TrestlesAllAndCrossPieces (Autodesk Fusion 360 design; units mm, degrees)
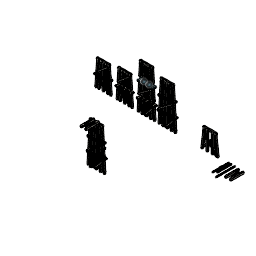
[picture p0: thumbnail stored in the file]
parameter "d35" = 40
parameter "d36" = 14
parameter "d37" = 14
sketch "Sketch1" plane through (0, 0, 0) normal (0, 0, 1) x axis (1, 0, 0)
  line L1 (1, 0) -> (0, 0)
  line L2 (1, 2) -> (1, 0)
  line L3 (0, 2) -> (1, 2)
  line L4 (0, 0) -> (0, 2)
  point P1 (0, 0)
  point P2 (0, 0)
  point P3 (1, 0)
  point P5 (0, 2)
  horizontal L1
  vertical L2
  horizontal L3
  vertical L4
  coincident P1 P2
  dimension "d1" distance P2 P3 = 1
  dimension "d2" distance P2 P5 = 2
sketch "Sketch2" plane through (0, 0, 0) normal (0, 0, 1) x axis (1, 0, 0)
  line L1 (-6.5, 0) -> (-5, 0)
  line L2 (-6.5, 2) -> (-6.5, 0)
  line L3 (-5, 2) -> (-6.5, 2)
  line L4 (-5, 0) -> (-5, 2)
  line L5 (-11.5, 0) -> (-10, 0)
  line L6 (-11.5, 2) -> (-11.5, 0)
  line L7 (-10, 2) -> (-11.5, 2)
  line L8 (-10, 0) -> (-10, 2)
  point P2 (-5, 0)
  point P3 (-6.5, 0)
  point P5 (-5, 2)
  point P6 (-10, 0)
  point P7 (-11.5, 0)
  point P9 (-10, 2)
  horizontal L1
  vertical L2
  horizontal L3
  vertical L4
  horizontal L5
  vertical L6
  horizontal L7
  vertical L8
  dimension "d5" distance P2 P3 = 1.5
  dimension "d6" distance P2 P5 = 2
  dimension "d7" distance P6 P7 = 1.5
  dimension "d8" distance P6 P9 = 2
extrude "Extrude2" new body sketch "Sketch2" profile of L1 L2 L3 L4 along normal blind 31 bodies "CrossPieceHorz31mm"
extrude "Extrude3" new body sketch "Sketch2" profile of L5 L6 L7 L8 along normal blind 36 bodies "CrossPieceDiagonal"
work_plane "WorkPlane1"
sketch "Sketch3" plane through (0, 2, 0) normal (0, 1, 0) x axis (-1, 0, 0)
  line L1 (11.5, 0) -> (10, 0)
  line L2 (11.5, 36) -> (11.5, 0)
  line L3 (10, 36) -> (11.5, 36)
  line L4 (10, 0) -> (10, 36)
  line L5 (10.75, 18) -> (10, 18)
  line L6 (10.75, 19.5) -> (10.75, 18)
  line L7 (10, 19.5) -> (10.75, 19.5)
  line L8 (10, 18) -> (10, 19.5)
  line L9 (10.75, 18) -> (10, 18)
  line L10 (10.75, 16.5) -> (10.75, 18)
  line L11 (10, 16.5) -> (10.75, 16.5)
  line L12 (10, 18) -> (10, 16.5)
  point P6 (10, 18)
  point P7 (10.75, 18)
  point P9 (10, 19.5)
  point P12 (10, 16.5)
  horizontal L5
  vertical L6
  horizontal L7
  vertical L8
  midpoint L4 P6
  horizontal L9
  vertical L10
  horizontal L11
  vertical L12
  dimension "d13" distance P6 P7 = 0.75
  dimension "d14" distance P6 P9 = 1.5
  dimension "d15" distance P6 P12 = 1.5
extrude "Extrude4" cut sketch "Sketch3" profile of L4 L5 L6 L7 L8 L9 L10 L11 L12 against normal blind 2.162
sketch "Sketch4" plane through (-10, 0, 0) normal (1, 0, 0) x axis (0, 0, -1)
  line L1 (-19.5, 2) -> (-19.5, 0)
  line L2 (-36, 2) -> (-19.5, 2)
  line L3 (-36, 0) -> (-36, 2)
  line L4 (-19.5, 0) -> (-36, 0)
  line L5 (-21.5, 0) -> (-19.5, 2)
  line L6 (-14.5, 2) -> (-16.5, 0)
  line L7 (-16.5, 2) -> (-14.5, 2)
  line L8 (-16.5, 0) -> (-16.5, 2)
  point P3 (-19.5, 2)
  point P6 (-19.5, 2)
  point P7 (-21.5, 0)
  coincident P3 P6
  coincident L4 P7
  parallel L5 L6
  parallel L4 L7
  perpendicular L7 L8
extrude "Extrude5" cut sketch "Sketch4" profile of L1 L4 L5 against normal blind 0.75
extrude "Extrude6" cut sketch "Sketch4" profile of L6 L7 L8 against normal blind 0.75
sketch "Sketch6" plane through (-11.5, 0, 0) normal (-1, 0, 0) x axis (0, 0, 1)
  line L1 (0, 0) -> (0, 2)
  line L2 (36, 0) -> (0, 0)
  line L3 (36, 2) -> (36, 0)
  line L4 (0, 2) -> (36, 2)
  line L5 (14, 2) -> (22, 2)
  line L6 (14, -0.0152) -> (14, 2)
  line L7 (22, -0.0152) -> (14, -0.0152)
  line L8 (22, 2) -> (22, -0.0152)
  line L9 (14, -0.0152) -> (22, 2)
  line L10 (22, -0.0152) -> (14, 2)
  point P10 (18, 0.9924)
  point P8 (14, -0.0152)
  point P9 (22, -0.0152)
  horizontal L5
  perpendicular L5 L6
  parallel L5 L7
  parallel L6 L8
  coincident L9 P10
  coincident L10 P10
  dimension "d22" distance P8 P9 = 8
extrude "Extrude7" add sketch "Sketch6" profile of L2 L4 L5 L6 L8 along normal blind 0.75
fillet "Fillet1" radius 1.5
fillet "Fillet2" radius 1.5
copy_paste_bodies "CopyPasteBodies1"
move "Move1"
extrude "Extrude8" add of existing geometry blind 10
sketch "Sketch7" plane through (0, 0, 0) normal (0, 0, 1) x axis (1, 0, 0)
  line L1 (13, 0) -> (10, 0)
  line L2 (13, 3.5) -> (13, 0)
  line L3 (10, 3.5) -> (13, 3.5)
  line L4 (10, 0) -> (10, 3.5)
  line L5 (11, 0) -> (13, 0)
  line L6 (11, 2) -> (11, 0)
  line L7 (13, 2) -> (11, 2)
  line L8 (13, 0) -> (13, 2)
  point P2 (10, 0)
  point P3 (13, 0)
  point P5 (10, 3.5)
  horizontal L1
  vertical L2
  horizontal L3
  vertical L4
  horizontal L5
  vertical L6
  horizontal L7
  vertical L8
  dimension "d31" distance P2 P3 = 3
  dimension "d32" distance P2 P5 = 3.5
extrude "Extrude9" new body sketch "Sketch7" along normal blind 28 bodies "TopPiecePose"
copy_paste_bodies "CopyPasteBodies2"
move "Move2"
sketch "Sketch9" plane through (0, 0, 28) normal (0, 0, 1) x axis (1, 0, 0)
  line L1 (20, 3.5) -> (23, 3.5)
  line L2 (20, 0) -> (20, 3.5)
  line L3 (23, 0) -> (20, 0)
  line L4 (23, 3.5) -> (23, 0)
  line L5 (22, 0) -> (20, 0)
  line L6 (22, 2) -> (22, 0)
  line L7 (20, 2) -> (22, 2)
  line L8 (20, 0) -> (20, 2)
  point P4 (20, 0)
  point P6 (20, 0)
  horizontal L5
  vertical L6
  horizontal L7
  vertical L8
  coincident P4 P6
loft "Loft2" sketch "Sketch9" + "Sketch7" bodies "TopPiece (1)"
sketch "Sketch11" plane through (0, 0, 0) normal (0, 0, 1) x axis (1, 0, 0)
  line L1 (-50, 43) -> (-50, 0)
  line L2 (-36, 43) -> (-50, 43)
  line L3 (-64, 43) -> (-50, 43)
  line L4 (-36, 43) -> (-64, 43)
  line L5 (-36, 40) -> (-36, 43)
  line L6 (-64, 40) -> (-36, 40)
  line L7 (-64, 43) -> (-64, 40)
  line L8 (-57, 40) -> (-54, 40)
  line L9 (-57, 0) -> (-57, 40)
  line L10 (-54, 0) -> (-57, 0)
  line L11 (-54, 40) -> (-54, 0)
  line L12 (-43, 40) -> (-46, 40)
  line L13 (-43, 0) -> (-43, 40)
  line L14 (-46, 0) -> (-43, 0)
  line L15 (-46, 40) -> (-46, 0)
  line L16 (-68, 0) -> (-63, 40)
  line L17 (-65, 0) -> (-68, 0)
  line L18 (-60, 40) -> (-65, 0)
  line L19 (-40, 40) -> (-35, 0)
  line L20 (-32, 0) -> (-37, 40)
  line L21 (-68, 0) -> (-65, 0)
  line L22 (-35, 0) -> (-32, 0)
  point P9 (-54, 40)
  point P13 (-46, 40)
  point P17 (-63, 40)
  point P20 (-60, 40)
  point P22 (-40, 40)
  point P23 (-37, 40)
  point P2 (-50, 0)
  point P3 (-50, 43)
  point P4 (-36, 43)
  point P5 (-64, 43)
  point P15 (-43, 0)
  point P16 (-46, 0)
  point P11 (-57, 0)
  point P12 (-54, 0)
  point P21 (-35, 0)
  point P24 (-32, 0)
  point P18 (-68, 0)
  point P19 (-65, 0)
  vertical L1
  perpendicular L1 L2
  perpendicular L1 L3
  horizontal L4
  vertical L5
  horizontal L6
  vertical L7
  horizontal L8
  vertical L9
  horizontal L10
  vertical L11
  coincident L6 P9
  horizontal L12
  vertical L13
  horizontal L14
  vertical L15
  coincident L6 P13
  coincident L6 P17
  perpendicular L9 L17
  coincident L6 P20
  parallel L16 L18
  coincident L6 P22
  coincident L6 P23
  parallel L19 L20
  parallel L21 L22
  dimension "d38" distance P2 P3 = 43
  dimension "d39" distance P3 P4 = 14
  dimension "d40" distance P3 P5 = 14
  dimension "d41" distance P15 P16 = 3
  dimension "d42" distance P11 P12 = 3
  dimension "d43" distance P21 P24 = 3
  dimension "d44" distance P18 P19 = 3
extrude "Extrude10" new body sketch "Sketch11" profile of L4 L5 L6 L7 L8 L9 L10 L11 L12 L13 L14 L15 L16 L17 L18 L19 L20 L21 L22 along normal blind 3 bodies "TrestleUpTo20Feet"
sketch "Sketch12" plane through (0, 0, 3) normal (0, 0, 1) x axis (1, 0, 0)
  line L1 (-68, 0) -> (-63, 40)
  line L2 (-65, 0) -> (-68, 0)
  line L3 (-60, 40) -> (-65, 0)
  line L4 (-57, 40) -> (-60, 40)
  line L5 (-57, 0) -> (-57, 40)
  line L6 (-54, 0) -> (-57, 0)
  line L7 (-54, 40) -> (-54, 0)
  line L8 (-46, 40) -> (-54, 40)
  line L9 (-46, 0) -> (-46, 40)
  line L10 (-43, 0) -> (-46, 0)
  line L11 (-43, 40) -> (-43, 0)
  line L12 (-40, 40) -> (-43, 40)
  line L13 (-35, 0) -> (-40, 40)
  line L14 (-32, 0) -> (-35, 0)
  line L15 (-37, 40) -> (-32, 0)
  line L16 (-36, 40) -> (-37, 40)
  line L17 (-36, 43) -> (-36, 40)
  line L18 (-64, 43) -> (-36, 43)
  line L19 (-64, 40) -> (-64, 43)
  line L20 (-63, 40) -> (-64, 40)
  line L21 (-35, 1) -> (-63.3758, 36.9935)
  line L22 (-33.0367, 2.5478) -> (-35, 1)
  line L23 (-61.4017, 38.5276) -> (-33.0367, 2.5478)
  line L24 (-63.3758, 36.9935) -> (-61.4017, 38.5276)
  point P22 (-63.3758, 36.9935)
  point P23 (-35, 1)
  point P24 (-33.0367, 2.5478)
  coincident L1 P22
  perpendicular L21 L22
  perpendicular L22 L23
  dimension "d47" distance P23 P24 = 2.5
extrude "Extrude11" add sketch "Sketch12" profile of L3 L5 L7 L9 L11 L13 L21 L22 L23 L24 along normal blind 1.5
sketch "Sketch13" plane through (0, 0, 0) normal (0, 0, -1) x axis (-1, 0, 0)
  line L1 (63, 40) -> (68, 0)
  line L2 (64, 40) -> (63, 40)
  line L3 (64, 43) -> (64, 40)
  line L4 (36, 43) -> (64, 43)
  line L5 (36, 40) -> (36, 43)
  line L6 (37, 40) -> (36, 40)
  line L7 (32, 0) -> (37, 40)
  line L8 (35, 0) -> (32, 0)
  line L9 (40, 40) -> (35, 0)
  line L10 (43, 40) -> (40, 40)
  line L11 (43, 0) -> (43, 40)
  line L12 (46, 0) -> (43, 0)
  line L13 (46, 40) -> (46, 0)
  line L14 (54, 40) -> (46, 40)
  line L15 (54, 0) -> (54, 40)
  line L16 (57, 0) -> (54, 0)
  line L17 (57, 40) -> (57, 0)
  line L18 (60, 40) -> (57, 40)
  line L19 (65, 0) -> (60, 40)
  line L20 (68, 0) -> (65, 0)
  line L21 (65, 2) -> (36.6252, 37.0014)
  line L22 (66.942, 3.5743) -> (65, 2)
  line L23 (38, 38) -> (66.942, 3.5743)
  line L24 (36.6252, 37.0014) -> (38, 38)
  point P22 (36.6252, 37.0014)
  point P23 (65, 2)
  point P24 (66.942, 3.5743)
  coincident L7 P22
  perpendicular L21 L22
  dimension "d50" distance P23 P24 = 2.5
extrude "Extrude12" add sketch "Sketch13" profile of L9 L11 L13 L15 L17 L19 L21 L22 L23 L24 along normal blind 1.5
sketch "Sketch14" plane through (0, 0, 0) normal (0, 0, 1) x axis (1, 0, 0)
  line L1 (-140, 87) -> (-140, 0)
  line L2 (-126, 87) -> (-140, 87)
  line L3 (-154, 87) -> (-140, 87)
  line L4 (-126, 87) -> (-154, 87)
  line L5 (-126, 84) -> (-126, 87)
  line L6 (-154, 84) -> (-126, 84)
  line L7 (-154, 87) -> (-154, 84)
  line L8 (-141.5, 84) -> (-140, 84)
  line L9 (-138.5, 84) -> (-141.5, 84)
  line L10 (-138.5, 0) -> (-138.5, 84)
  line L11 (-141.5, 0) -> (-138.5, 0)
  line L12 (-141.5, 84) -> (-141.5, 0)
  line L13 (-132.5, -0.5) -> (-137.5298, 84)
  line L14 (-129.5004, -0.5) -> (-132.5, -0.5)
  line L15 (-129.5053, -0.3213) -> (-129.5004, -0.5)
  line L16 (-134.5245, 84) -> (-129.5053, -0.3213)
  line L17 (-121.5, 0) -> (-126.5019, 84.0326)
  line L18 (-124.5, 0) -> (-121.5, 0)
  line L19 (-129.5, 84) -> (-124.5, 0)
  line L20 (-141.5, 0) -> (-141.5, 84)
  line L21 (-145.4756, 84) -> (-150.4947, -0.3213)
  line L22 (-154, 87) -> (-140, 87)
  line L23 (-150.5, 84) -> (-155.5, 0)
  line L24 (-147.5, -0.5) -> (-142.4702, 84)
  line L25 (-150.4947, -0.3213) -> (-150.4996, -0.5)
  line L26 (-158.5, 0) -> (-153.4981, 84.0326)
  line L27 (-150.4996, -0.5) -> (-147.5, -0.5)
  line L28 (-155.5, 0) -> (-158.5, 0)
  line L29 (-154, 84) -> (-154, 87)
  point P9 (-140, 84)
  point P14 (-137.5298, 84)
  point P18 (-134.5245, 84)
  point P22 (-129.5, 84)
  point P2 (-140, 0)
  point P27 (-140, 0)
  point P3 (-140, 87)
  point P30 (-140, 87)
  point P4 (-126, 87)
  point P26 (-154, 87)
  point P6 (-126, 87)
  point P28 (-154, 87)
  point P7 (-126, 84)
  point P32 (-154, 84)
  point P25 (-140, 84)
  point P10 (-141.5, 84)
  point P23 (-138.5, 84)
  point P11 (-138.5, 84)
  point P36 (-141.5, 84)
  point P12 (-138.5, 0)
  point P41 (-141.5, 0)
  point P13 (-141.5, 0)
  point P38 (-138.5, 0)
  point P35 (-142.4702, 84)
  point P15 (-132.5, -0.5)
  point P37 (-147.5, -0.5)
  point P16 (-129.5053, -0.3213)
  point P39 (-150.4947, -0.3213)
  point P17 (-129.5004, -0.5)
  point P40 (-150.4996, -0.5)
  point P24 (-145.4756, 84)
  point P19 (-126.5019, 84.0326)
  point P34 (-153.4981, 84.0326)
  point P20 (-121.5, 0)
  point P31 (-158.5, 0)
  point P21 (-124.5, 0)
  point P33 (-155.5, 0)
  point P29 (-150.5, 84)
  point P5 (-154, 87)
  point P8 (-154, 84)
  vertical L1
  perpendicular L1 L2
  perpendicular L1 L3
  horizontal L4
  vertical L5
  horizontal L6
  vertical L7
  midpoint L6 P9
  perpendicular L1 L8
  horizontal L9
  vertical L10
  horizontal L11
  vertical L12
  coincident L6 P14
  horizontal L14
  coincident L6 P18
  parallel L13 L16
  parallel L16 L17
  horizontal L18
  coincident L6 P22
  parallel L17 L19
  symmetric P2 L1 P27
  symmetric P3 L1 P30
  symmetric L1 P4 P26
  symmetric L1 P6 P28
  symmetric L1 P7 P32
  symmetric L1 P9 P25
  symmetric L1 P10 P23
  symmetric L1 P11 P36
  symmetric L1 P12 P41
  symmetric L1 P13 P38
  symmetric L1 P14 P35
  symmetric L1 P15 P37
  symmetric L1 P16 P39
  symmetric L1 P17 P40
  symmetric L1 P18 P24
  symmetric L1 P19 P34
  symmetric L1 P20 P31
  symmetric L1 P21 P33
  symmetric L1 P22 P29
  dimension "d53" distance P2 P3 = 87
  dimension "d54" distance P3 P4 = 14
  dimension "d55" distance P3 P5 = 14
  dimension "d56" distance P5 P8 = 3
  dimension "d57" distance P9 P10 = 1.5
  dimension "d58" distance P10 P11 = 3
  dimension "d59" distance P11 P12 = 84
  dimension "d60" distance P15 P16 = 3
  dimension "d62" distance P20 P21 = 3
extrude "Extrude13" new body sketch "Sketch14" profile of L4 L5 L6 L7 L9 L10 L11 L12 L13 L14 L15 L16 L17 L18 L19 L20 L21 L23 L24 L25 L26 L27 L28 L29 along normal blind 3 bodies "Trestle32FeetTo72Feet"
sketch "Sketch15" plane through (0, 0, 3) normal (0, 0, 1) x axis (1, 0, 0)
  line L1 (-154, 87) -> (-126, 87)
  line L2 (-154, 84) -> (-154, 87)
  line L3 (-153.5, 84) -> (-154, 84)
  line L4 (-158.5, 0) -> (-153.5, 84)
  line L5 (-155.5, 0) -> (-158.5, 0)
  line L6 (-150.5, 84) -> (-155.5, 0)
  line L7 (-145.4756, 84) -> (-150.5, 84)
  line L8 (-150.4947, -0.3213) -> (-145.4756, 84)
  line L9 (-150.4996, -0.5) -> (-150.4947, -0.3213)
  line L10 (-147.5, -0.5) -> (-150.4996, -0.5)
  line L11 (-142.4702, 84) -> (-147.5, -0.5)
  line L12 (-141.5, 84) -> (-142.4702, 84)
  line L13 (-141.5, 0) -> (-141.5, 84)
  line L14 (-138.5, 0) -> (-141.5, 0)
  line L15 (-138.5, 84) -> (-138.5, 0)
  line L16 (-137.5298, 84) -> (-138.5, 84)
  line L17 (-132.5, -0.5) -> (-137.5298, 84)
  line L18 (-129.5004, -0.5) -> (-132.5, -0.5)
  line L19 (-129.5053, -0.3213) -> (-129.5004, -0.5)
  line L20 (-134.5245, 84) -> (-129.5053, -0.3213)
  line L21 (-129.5, 84) -> (-134.5245, 84)
  line L22 (-124.5, 0) -> (-129.5, 84)
  line L23 (-121.5, 0) -> (-124.5, 0)
  line L24 (-126.5, 84) -> (-121.5, 0)
  line L25 (-126, 84) -> (-126.5, 84)
  line L26 (-126, 87) -> (-126, 84)
  line L27 (-138.0149, 56) -> (-138.0149, 84)
  line L28 (-119.2649, 56) -> (-138.0149, 56)
  line L29 (-138.0149, 28) -> (-138.0149, 56)
  line L30 (-116.2649, 28) -> (-138.0149, 28)
  line L31 (-156.4252, 56) -> (-123, 56)
  line L32 (-156.4252, 53.5) -> (-156.4252, 56)
  line L33 (-123, 53.5) -> (-156.4252, 53.5)
  line L34 (-123, 56) -> (-123, 53.5)
  line L35 (-158, 28) -> (-121, 28)
  line L36 (-158, 25.5) -> (-158, 28)
  line L37 (-121, 25.5) -> (-158, 25.5)
  line L38 (-121, 28) -> (-121, 25.5)
  point P28 (-138.0149, 84)
  point P33 (-123, 56)
  point P37 (-121, 28)
  point P29 (-138.0149, 56)
  point P31 (-138.0149, 28)
  point P36 (-123, 53.5)
  point P40 (-121, 25.5)
  midpoint L16 P28
  perpendicular L16 L27
  perpendicular L27 L28
  perpendicular L28 L29
  perpendicular L29 L30
  horizontal L31
  vertical L32
  horizontal L33
  vertical L34
  coincident L28 P33
  horizontal L35
  vertical L36
  horizontal L37
  vertical L38
  coincident L30 P37
  dimension "d65" distance P28 P29 = 28
  dimension "d66" distance P29 P31 = 28
  dimension "d67" distance P33 P36 = 2.5
  dimension "d68" distance P37 P40 = 2.5
extrude "Extrude14" new body sketch "Sketch15" profile of L4 L6 L8 L11 L13 L15 L17 L20 L22 L24 L31 L32 L33 L34 L35 L36 L37 L38 along normal blind 2.5
copy_paste_bodies "CopyPasteBodies3"
move "Move3"
combine "Combine1"
sketch "Sketch16" plane through (0, 0, 3) normal (0, 0, 1) x axis (1, 0, 0)
  line L1 (-152.1667, 56) -> (-155.1667, 56)
  line L2 (-150.5, 84) -> (-152.1667, 56)
  line L3 (-145.4756, 84) -> (-150.5, 84)
  line L4 (-147.1422, 56) -> (-145.4756, 84)
  line L5 (-144.1369, 56) -> (-147.1422, 56)
  line L6 (-142.4702, 84) -> (-144.1369, 56)
  line L7 (-141.5, 84) -> (-142.4702, 84)
  line L8 (-141.5, 56) -> (-141.5, 84)
  line L9 (-138.5, 56) -> (-141.5, 56)
  line L10 (-138.5, 84) -> (-138.5, 56)
  line L11 (-137.5298, 84) -> (-138.5, 84)
  line L12 (-135.8631, 56) -> (-137.5298, 84)
  line L13 (-132.8578, 56) -> (-135.8631, 56)
  line L14 (-134.5245, 84) -> (-132.8578, 56)
  line L15 (-129.5, 84) -> (-134.5245, 84)
  line L16 (-127.8333, 56) -> (-129.5, 84)
  line L17 (-124.8333, 56) -> (-127.8333, 56)
  line L18 (-126.5, 84) -> (-124.8333, 56)
  line L19 (-126, 84) -> (-126.5, 84)
  line L20 (-126, 87) -> (-126, 84)
  line L21 (-154, 87) -> (-126, 87)
  line L22 (-154, 84) -> (-154, 87)
  line L23 (-153.5, 84) -> (-154, 84)
  line L24 (-155.1667, 56) -> (-153.5, 84)
  line L25 (-125.5862, 59.4116) -> (-151.3333, 83.3591)
  line L26 (-127.2889, 57.581) -> (-125.5862, 59.4116)
  line L27 (-153.2104, 81.6907) -> (-127.2889, 57.581)
  line L28 (-153.2104, 81.6907) -> (-151.3333, 83.3591)
  line L29 (-155, 29) -> (-125, 51)
  line L30 (-156.4784, 31.016) -> (-155, 29)
  line L31 (-126.9904, 52.6406) -> (-156.4784, 31.016)
  line L32 (-125, 51) -> (-126.9904, 52.6406)
  point P27 (-125.5862, 59.4116)
  point P28 (-127.2889, 57.581)
  point P31 (-155, 29)
  point P32 (-156.4784, 31.016)
  perpendicular L25 L26
  perpendicular L26 L27
  perpendicular L29 L30
  perpendicular L30 L31
  dimension "d71" distance P27 P28 = 2.5
  dimension "d72" distance P31 P32 = 2.5
extrude "Extrude15" add sketch "Sketch16" profile of L2 L4 L6 L8 L10 L12 L14 L16 L25 L26 L27 L28 L29 L30 L31 L32 along normal blind 1.5
sketch "Sketch17" plane through (0, 0, 0) normal (0, 0, -1) x axis (-1, 0, 0)
  line L1 (127.8333, 56) -> (124.8333, 56)
  line L2 (129.5, 84) -> (127.8333, 56)
  line L3 (134.5245, 84) -> (129.5, 84)
  line L4 (132.8578, 56) -> (134.5245, 84)
  line L5 (135.8631, 56) -> (132.8578, 56)
  line L6 (137.5298, 84) -> (135.8631, 56)
  line L7 (138.5, 84) -> (137.5298, 84)
  line L8 (138.5, 56) -> (138.5, 84)
  line L9 (141.5, 56) -> (138.5, 56)
  line L10 (141.5, 84) -> (141.5, 56)
  line L11 (142.4702, 84) -> (141.5, 84)
  line L12 (144.1369, 56) -> (142.4702, 84)
  line L13 (147.1422, 56) -> (144.1369, 56)
  line L14 (145.4756, 84) -> (147.1422, 56)
  line L15 (150.5, 84) -> (145.4756, 84)
  line L16 (152.1667, 56) -> (150.5, 84)
  line L17 (155.1667, 56) -> (152.1667, 56)
  line L18 (153.5, 84) -> (155.1667, 56)
  line L19 (154, 84) -> (153.5, 84)
  line L20 (154, 87) -> (154, 84)
  line L21 (126, 87) -> (154, 87)
  line L22 (126, 84) -> (126, 87)
  line L23 (126.5, 84) -> (126, 84)
  line L24 (124.8333, 56) -> (126.5, 84)
  line L25 (154.5, 58.5) -> (129, 83.5)
  line L26 (152.7498, 56.7148) -> (154.5, 58.5)
  line L27 (126.9694, 81.9897) -> (152.7498, 56.7148)
  line L28 (126.9694, 81.9897) -> (129, 83.5)
  line L29 (123.47, 31.0364) -> (153, 53)
  line L30 (124.962, 29.0305) -> (123.47, 31.0364)
  line L31 (154.7403, 51.1787) -> (124.962, 29.0305)
  line L32 (153, 53) -> (154.7403, 51.1787)
  point P27 (154.5, 58.5)
  point P28 (152.7498, 56.7148)
  point P31 (123.47, 31.0364)
  point P32 (124.962, 29.0305)
  perpendicular L25 L26
  perpendicular L26 L27
  parallel L28 L29
  perpendicular L29 L30
  perpendicular L30 L31
  dimension "d76" distance P27 P28 = 2.5
  dimension "d77" distance P31 P32 = 2.5
extrude "Extrude16" add sketch "Sketch17" profile of L2 L4 L6 L8 L10 L12 L14 L16 L25 L26 L27 L28 L29 L30 L31 L32 along normal blind 1.5
sketch "Sketch18" plane through (0, 0, 0) normal (0, 0, -1) x axis (-1, 0, 0)
  line L1 (138.5, 25.5) -> (141.5, 25.5)
  line L2 (138.5, 0) -> (138.5, 25.5)
  line L3 (141.5, 0) -> (138.5, 0)
  line L4 (141.5, 25.5) -> (141.5, 0)
  line L5 (124, 1) -> (140, 22)
  line L6 (122.0114, 2.5151) -> (124, 1)
  line L7 (138.3949, 24.0184) -> (122.0114, 2.5151)
  line L8 (139.07, 24.9045) -> (138.3949, 24.0184)
  line L9 (158, 3) -> (141, 22.5)
  line L10 (156.1156, 1.3572) -> (158, 3)
  line L11 (139.3737, 20.5611) -> (156.1156, 1.3572)
  line L12 (139.3737, 20.5611) -> (141, 22.5)
  line L13 (141.0586, 23.3894) -> (139.07, 24.9045)
  line L14 (140, 22) -> (141.0586, 23.3894)
  point P7 (124, 1)
  point P8 (122.0114, 2.5151)
  point P12 (158, 3)
  point P13 (156.1156, 1.3572)
  point P10 (139.07, 24.9045)
  point P15 (141.0586, 23.3894)
  perpendicular L5 L6
  perpendicular L6 L7
  parallel L7 L8
  perpendicular L9 L10
  perpendicular L10 L11
  perpendicular L8 L13
  dimension "d82" distance P7 P8 = 2.5
  dimension "d83" distance P12 P13 = 2.5
  dimension "d84" distance P10 P15 = 2.5
extrude "Extrude17" add sketch "Sketch18" profile of L2 L4 L5 L6 L7 L8 L9 L10 L11 L12 L13 L14 along normal blind 1.5
sketch "Sketch19" plane through (0, 0, 3) normal (0, 0, 1) x axis (1, 0, 0)
  line L1 (-156.9821, 25.5) -> (-153.9821, 25.5)
  line L2 (-158.5, 0) -> (-156.9821, 25.5)
  line L3 (-155.5, 0) -> (-158.5, 0)
  line L4 (-153.9821, 25.5) -> (-155.5, 0)
  line L5 (-139, 2.5) -> (-154.5, 25)
  line L6 (-141.0588, 1.0817) -> (-139, 2.5)
  line L7 (-156.8923, 24.0659) -> (-141.0588, 1.0817)
  line L8 (-156.8923, 24.0659) -> (-154.5, 25)
  line L9 (-140.6793, 5.852) -> (-139, 4)
  line L10 (-123, 23) -> (-139, 4)
  line L11 (-124.9123, 24.6103) -> (-123, 23)
  line L12 (-140.6793, 5.852) -> (-124.9123, 24.6103)
  point P7 (-139, 2.5)
  point P8 (-141.0588, 1.0817)
  point P10 (-139, 4)
  point P11 (-140.6793, 5.852)
  point P12 (-123, 23)
  point P13 (-124.9123, 24.6103)
  perpendicular L5 L6
  perpendicular L6 L7
  perpendicular L10 L11
  dimension "d87" distance P7 P8 = 2.5
  dimension "d88" distance P10 P11 = 2.5
  dimension "d89" distance P12 P13 = 2.5
extrude "Extrude18" add sketch "Sketch19" profile of L4 L5 L6 L7 L8 L9 L10 L11 L12 along normal blind 1.5
sketch "Sketch20" plane through (0, 0, 0) normal (0, 0, 1) x axis (1, 0, 0)
  line L1 (-275, 56) -> (-275, 0)
  line L2 (-261, 56) -> (-275, 56)
  line L3 (-289, 56) -> (-275, 56)
  line L4 (-289, 56) -> (-261, 56)
  line L5 (-289, 53) -> (-289, 56)
  line L6 (-261, 53) -> (-289, 53)
  line L7 (-261, 56) -> (-261, 53)
  line L8 (-273.5, 53) -> (-276.5, 53)
  line L9 (-273.5, 0) -> (-273.5, 53)
  line L10 (-276.5, 0) -> (-273.5, 0)
  line L11 (-276.5, 53) -> (-276.5, 0)
  line L12 (-258, 0) -> (-262, 53)
  line L13 (-261.0085, 0) -> (-258, 0)
  line L14 (-265.0085, 53) -> (-261.0085, 0)
  line L15 (-264, 0) -> (-268, 53)
  line L16 (-267, 0) -> (-264, 0)
  line L17 (-271, 53) -> (-267, 0)
  line L18 (-288.9915, 0) -> (-292, 0)
  line L19 (-283, 0) -> (-286, 0)
  line L20 (-279, 53) -> (-283, 0)
  line L21 (-284.9915, 53) -> (-288.9915, 0)
  line L22 (-292, 0) -> (-288, 53)
  line L23 (-286, 0) -> (-282, 53)
  point P9 (-276.5, 53)
  point P16 (-265.0085, 53)
  point P17 (-268, 53)
  point P20 (-271, 53)
  point P8 (-261, 53)
  point P22 (-289, 53)
  point P13 (-262, 53)
  point P23 (-288, 53)
  point P14 (-258, 0)
  point P24 (-292, 0)
  point P15 (-261.0085, 0)
  point P25 (-288.9915, 0)
  point P29 (-284.9915, 53)
  point P27 (-282, 53)
  point P18 (-264, 0)
  point P28 (-286, 0)
  point P19 (-267, 0)
  point P26 (-283, 0)
  point P21 (-279, 53)
  point P2 (-275, 0)
  point P3 (-275, 56)
  point P5 (-289, 56)
  point P11 (-273.5, 0)
  point P12 (-276.5, 0)
  vertical L1
  perpendicular L1 L2
  perpendicular L1 L3
  horizontal L4
  vertical L5
  horizontal L6
  vertical L7
  horizontal L8
  vertical L9
  horizontal L10
  vertical L11
  coincident L6 P9
  horizontal L13
  coincident L6 P16
  parallel L12 L14
  coincident L6 P17
  parallel L14 L15
  coincident L6 P20
  parallel L15 L17
  symmetric L1 P8 P22
  symmetric L1 P13 P23
  symmetric L1 P14 P24
  symmetric L1 P15 P25
  symmetric L1 P16 P29
  symmetric L1 P17 P27
  symmetric L1 P18 P28
  symmetric L1 P19 P26
  symmetric L1 P20 P21
  dimension "d92" distance P2 P3 = 56
  dimension "d93" distance P3 P5 = 14
  dimension "d94" distance P11 P12 = 3
extrude "Extrude19" new body sketch "Sketch20" profile of L4 L5 L6 L7 L8 L9 L10 L11 L12 L13 L14 L15 L16 L17 L18 L19 L20 L21 L22 L23 along normal blind 3 bodies "Testle20To32Feet"
sketch "Sketch21" plane through (0, 0, 3) normal (0, 0, 1) x axis (1, 0, 0)
  line L1 (-261, 53) -> (-262, 53)
  line L2 (-261, 56) -> (-261, 53)
  line L3 (-289, 56) -> (-261, 56)
  line L4 (-289, 53) -> (-289, 56)
  line L5 (-288, 53) -> (-289, 53)
  line L6 (-292, 0) -> (-288, 53)
  line L7 (-288.9915, 0) -> (-292, 0)
  line L8 (-284.9915, 53) -> (-288.9915, 0)
  line L9 (-282, 53) -> (-284.9915, 53)
  line L10 (-286, 0) -> (-282, 53)
  line L11 (-283, 0) -> (-286, 0)
  line L12 (-279, 53) -> (-283, 0)
  line L13 (-276.5, 53) -> (-279, 53)
  line L14 (-276.5, 0) -> (-276.5, 53)
  line L15 (-273.5, 0) -> (-276.5, 0)
  line L16 (-273.5, 53) -> (-273.5, 0)
  line L17 (-271, 53) -> (-273.5, 53)
  line L18 (-267, 0) -> (-271, 53)
  line L19 (-264, 0) -> (-267, 0)
  line L20 (-268, 53) -> (-264, 0)
  line L21 (-265.0085, 53) -> (-268, 53)
  line L22 (-261.0085, 0) -> (-265.0085, 53)
  line L23 (-258, 0) -> (-261.0085, 0)
  line L24 (-262, 53) -> (-258, 0)
  line L25 (-275, 25) -> (-275, 53)
  line L26 (-292, 25) -> (-259, 25)
  line L27 (-292, 27.5) -> (-292, 25)
  line L28 (-259, 27.5) -> (-292, 27.5)
  line L29 (-259, 25) -> (-259, 27.5)
  point P26 (-275, 53)
  point P27 (-275, 25)
  point P28 (-259, 25)
  point P31 (-259, 27.5)
  parallel L16 L25
  horizontal L26
  vertical L27
  horizontal L28
  vertical L29
  dimension "d98" distance P26 P27 = 28
  dimension "d99" distance P28 P31 = 2.5
extrude "Extrude20" new body sketch "Sketch21" profile of L6 L8 L10 L12 L14 L16 L18 L20 L22 L24 L25 L26 L27 L28 L29 along normal blind 2.5
copy_paste_bodies "CopyPasteBodies4"
move "Move4"
combine "Combine2"
sketch "Sketch22" plane through (0, 0, 3) normal (0, 0, 1) x axis (1, 0, 0)
  line L1 (-286.916, 27.5) -> (-289.9245, 27.5)
  line L2 (-284.9915, 53) -> (-286.916, 27.5)
  line L3 (-282, 53) -> (-284.9915, 53)
  line L4 (-283.9245, 27.5) -> (-282, 53)
  line L5 (-280.9245, 27.5) -> (-283.9245, 27.5)
  line L6 (-279, 53) -> (-280.9245, 27.5)
  line L7 (-276.5, 53) -> (-279, 53)
  line L8 (-276.5, 27.5) -> (-276.5, 53)
  line L9 (-273.5, 27.5) -> (-276.5, 27.5)
  line L10 (-273.5, 53) -> (-273.5, 27.5)
  line L11 (-271, 53) -> (-273.5, 53)
  line L12 (-269.0755, 27.5) -> (-271, 53)
  line L13 (-266.0755, 27.5) -> (-269.0755, 27.5)
  line L14 (-268, 53) -> (-266.0755, 27.5)
  line L15 (-265.0085, 53) -> (-268, 53)
  line L16 (-263.084, 27.5) -> (-265.0085, 53)
  line L17 (-260.0755, 27.5) -> (-263.084, 27.5)
  line L18 (-262, 53) -> (-260.0755, 27.5)
  line L19 (-261, 53) -> (-262, 53)
  line L20 (-261, 56) -> (-261, 53)
  line L21 (-289, 56) -> (-261, 56)
  line L22 (-289, 53) -> (-289, 56)
  line L23 (-288, 53) -> (-289, 53)
  line L24 (-289.9245, 27.5) -> (-288, 53)
  line L25 (-289.0062, 31.0879) -> (-264.6658, 51.5236)
  line L26 (-287.3987, 29.1733) -> (-289.0062, 31.0879)
  line L27 (-262.2291, 50.3051) -> (-287.3987, 29.1733)
  line L28 (-264.6658, 51.5236) -> (-262.2291, 50.3051)
  line L29 (-258.7, 5) -> (-288, 24)
  line L30 (-260.0602, 2.9024) -> (-258.7, 5)
  line L31 (-289.8169, 22.1986) -> (-260.0602, 2.9024)
  line L32 (-288, 24) -> (-289.8169, 22.1986)
  point P27 (-289.0062, 31.0879)
  point P28 (-287.3987, 29.1733)
  point P31 (-258.7, 5)
  point P32 (-260.0602, 2.9024)
  perpendicular L25 L26
  perpendicular L26 L27
  perpendicular L29 L30
  perpendicular L30 L31
  dimension "d102" distance P27 P28 = 2.5
  dimension "d103" distance P31 P32 = 2.5
extrude "Extrude21" add sketch "Sketch22" profile of L2 L4 L6 L8 L10 L12 L14 L16 L25 L26 L27 L28 L29 L30 L31 L32 along normal blind 1.5
sketch "Sketch23" plane through (0, 0, 0) normal (0, 0, -1) x axis (-1, 0, 0)
  line L1 (263.084, 27.5) -> (260.0755, 27.5)
  line L2 (265.0085, 53) -> (263.084, 27.5)
  line L3 (268, 53) -> (265.0085, 53)
  line L4 (266.0755, 27.5) -> (268, 53)
  line L5 (269.0755, 27.5) -> (266.0755, 27.5)
  line L6 (271, 53) -> (269.0755, 27.5)
  line L7 (273.5, 53) -> (271, 53)
  line L8 (273.5, 27.5) -> (273.5, 53)
  line L9 (276.5, 27.5) -> (273.5, 27.5)
  line L10 (276.5, 53) -> (276.5, 27.5)
  line L11 (279, 53) -> (276.5, 53)
  line L12 (280.9245, 27.5) -> (279, 53)
  line L13 (283.9245, 27.5) -> (280.9245, 27.5)
  line L14 (282, 53) -> (283.9245, 27.5)
  line L15 (284.9915, 53) -> (282, 53)
  line L16 (286.916, 27.5) -> (284.9915, 53)
  line L17 (289.9245, 27.5) -> (286.916, 27.5)
  line L18 (288, 53) -> (289.9245, 27.5)
  line L19 (289, 53) -> (288, 53)
  line L20 (289, 56) -> (289, 53)
  line L21 (261, 56) -> (289, 56)
  line L22 (261, 53) -> (261, 56)
  line L23 (262, 53) -> (261, 53)
  line L24 (260.0755, 27.5) -> (262, 53)
  line L25 (260.9398, 31.0716) -> (285.7061, 51.8753)
  line L26 (262.5478, 29.1574) -> (260.9398, 31.0716)
  line L27 (288.1748, 50.684) -> (262.5478, 29.1574)
  line L28 (285.7061, 51.8753) -> (288.1748, 50.684)
  line L29 (291, 4) -> (262, 24)
  line L30 (289.5807, 1.942) -> (291, 4)
  line L31 (260.2095, 22.1979) -> (289.5807, 1.942)
  line L32 (262, 24) -> (260.2095, 22.1979)
  point P29 (288.1748, 50.684)
  point P27 (260.9398, 31.0716)
  point P28 (262.5478, 29.1574)
  point P31 (291, 4)
  point P32 (289.5807, 1.942)
  perpendicular L25 L26
  coincident L18 P29
  perpendicular L26 L27
  perpendicular L29 L30
  perpendicular L30 L31
  dimension "d106" distance P27 P28 = 2.5
  dimension "d107" distance P31 P32 = 2.5
extrude "Extrude22" add sketch "Sketch23" profile of L2 L4 L6 L8 L10 L12 L14 L16 L25 L26 L27 L28 L29 L30 L31 L32 along normal blind 1.5
copy_paste_bodies "CopyPasteBodies5"
move "Move5"
split "Split1" bodies "Testle20To32FeetSplitTop"
move "Move6"
sketch "Sketch24" plane through (0, 27.5, 0) normal (0, 1, 0) x axis (-1, 0, 0)
  line L1 (214, 0) -> (215.0755, 0)
  line L2 (214, -2.5) -> (214, 0)
  line L3 (247, -2.5) -> (214, -2.5)
  line L4 (247, 0) -> (247, -2.5)
  line L5 (244.9245, 0) -> (247, 0)
  line L6 (244.9245, 3) -> (244.9245, 0)
  line L7 (247, 3) -> (244.9245, 3)
  line L8 (247, 5.5) -> (247, 3)
  line L9 (214, 5.5) -> (247, 5.5)
  line L10 (214, 3) -> (214, 5.5)
  line L11 (215.0755, 3) -> (214, 3)
  line L12 (215.0755, 0) -> (215.0755, 3)
  line L13 (218.084, 3) -> (218.084, 0)
  line L14 (221.0755, 3) -> (218.084, 3)
  line L15 (221.0755, 0) -> (221.0755, 3)
  line L16 (218.084, 0) -> (221.0755, 0)
  line L17 (224.0755, 3) -> (224.0755, 0)
  line L18 (228.5, 3) -> (224.0755, 3)
  line L19 (228.5, 0) -> (228.5, 3)
  line L20 (224.0755, 0) -> (228.5, 0)
  line L21 (231.5, 3) -> (231.5, 0)
  line L22 (235.9245, 3) -> (231.5, 3)
  line L23 (235.9245, 0) -> (235.9245, 3)
  line L24 (231.5, 0) -> (235.9245, 0)
  line L25 (238.9245, 3) -> (238.9245, 0)
  line L26 (241.916, 3) -> (238.9245, 3)
  line L27 (241.916, 0) -> (241.916, 3)
  line L28 (238.9245, 0) -> (241.916, 0)
  line L29 (221.5, 2.5) -> (223.5, 2.5)
  line L30 (221.5, 0.5) -> (221.5, 2.5)
  line L31 (223.5, 0.5) -> (221.5, 0.5)
  line L32 (223.5, 2.5) -> (223.5, 0.5)
  line L33 (221.5, 0.5) -> (223.5, 2.5)
  line L34 (223.5, 0.5) -> (221.5, 2.5)
  line L35 (236.5, 0.5) -> (238.5, 0.5)
  line L36 (236.5, 2.5) -> (236.5, 0.5)
  line L37 (238.5, 2.5) -> (236.5, 2.5)
  line L38 (238.5, 0.5) -> (238.5, 2.5)
  line L39 (236.5, 2.5) -> (238.5, 0.5)
  line L40 (238.5, 2.5) -> (236.5, 0.5)
  point P34 (222.5, 1.5)
  point P39 (237.5, 1.5)
  point P32 (221.5, 0.5)
  point P33 (223.5, 0.5)
  point P31 (221.5, 2.5)
  point P37 (236.5, 2.5)
  point P38 (238.5, 2.5)
  point P36 (236.5, 0.5)
  horizontal L29
  perpendicular L29 L30
  parallel L29 L31
  parallel L30 L32
  coincident L33 P34
  coincident L34 P34
  horizontal L35
  perpendicular L35 L36
  parallel L35 L37
  parallel L36 L38
  coincident L39 P39
  coincident L40 P39
  dimension "d110" distance P32 P33 = 2
  dimension "d111" distance P31 P32 = 2
  dimension "d112" distance P37 P38 = 2
  dimension "d113" distance P36 P37 = 2
extrude "Extrude23" cut sketch "Sketch24" profile of L29 L30 L31 L32 L35 L36 L37 L38 against normal blind 2
sketch "Sketch25" plane through (0, 32.5, 0) normal (0, -1, 0) x axis (1, 0, 0)
  line L1 (-235.9245, 3) -> (-235.9245, 0)
  line L2 (-238.9245, 3) -> (-235.9245, 3)
  line L3 (-238.9245, 0) -> (-238.9245, 3)
  line L4 (-235.9245, 0) -> (-238.9245, 0)
  circle C1 centre (-237.5, 1.5) radius 0.75
  circle C2 centre (-222.5, 1.5) radius 0.75
  point P6 (-237.5, 1.5)
  point P8 (-237.5, 1.5)
  point P7 (-222.5, 1.5)
  point P9 (-222.5, 1.5)
  coincident P6 P8
  coincident P7 P9
  dimension "d116" diameter C1 = 1.5
  dimension "d117" diameter C2 = 1.5
extrude "Extrude24" add sketch "Sketch25" profile of C1 C2 along normal blind 1.5
copy_paste_bodies "CopyPasteBodies6"
move "Move7"
split "Split2" bodies "Trestle32FeetTo72FeetSplitMiddle"
move "Move8"
sketch "Sketch28" plane through (0, 28, 0) normal (0, 1, 0) x axis (-1, 0, 0)
  line L1 (165, 0) -> (167.1667, 0)
  line L2 (165, -2.5) -> (165, 0)
  line L3 (202, -2.5) -> (165, -2.5)
  line L4 (202, 0) -> (202, -2.5)
  line L5 (200.8333, 0) -> (202, 0)
  line L6 (200.8333, 3) -> (200.8333, 0)
  line L7 (202, 3) -> (200.8333, 3)
  line L8 (202, 5.5) -> (202, 3)
  line L9 (165, 5.5) -> (202, 5.5)
  line L10 (165, 3) -> (165, 5.5)
  line L11 (167.1667, 3) -> (165, 3)
  line L12 (167.1667, 0) -> (167.1667, 3)
  line L13 (170.1667, 3) -> (170.1667, 0)
  line L14 (175.1911, 3) -> (170.1667, 3)
  line L15 (175.1911, 0) -> (175.1911, 3)
  line L16 (170.1667, 0) -> (175.1911, 0)
  line L17 (178.1964, 3) -> (178.1964, 0)
  line L18 (182.5, 3) -> (178.1964, 3)
  line L19 (182.5, 0) -> (182.5, 3)
  line L20 (178.1964, 0) -> (182.5, 0)
  line L21 (185.5, 3) -> (185.5, 0)
  line L22 (189.8036, 3) -> (185.5, 3)
  line L23 (189.8036, 0) -> (189.8036, 3)
  line L24 (185.5, 0) -> (189.8036, 0)
  line L25 (192.8089, 3) -> (192.8089, 0)
  line L26 (197.8333, 3) -> (192.8089, 3)
  line L27 (197.8333, 0) -> (197.8333, 3)
  line L28 (192.8089, 0) -> (197.8333, 0)
  line L29 (190.3186, 2.5409) -> (192.3186, 2.5409)
  line L30 (190.3186, 0.5409) -> (190.3186, 2.5409)
  line L31 (192.3186, 0.5409) -> (190.3186, 0.5409)
  line L32 (192.3186, 2.5409) -> (192.3186, 0.5409)
  line L33 (190.3186, 0.5409) -> (192.3186, 2.5409)
  line L34 (192.3186, 0.5409) -> (190.3186, 2.5409)
  line L35 (177.7, 2.6) -> (175.7, 2.6)
  line L36 (177.7, 0.6) -> (177.7, 2.6)
  line L37 (175.7, 0.6) -> (177.7, 0.6)
  line L38 (175.7, 2.6) -> (175.7, 0.6)
  line L39 (177.7, 0.6) -> (175.7, 2.6)
  line L40 (175.7, 0.6) -> (177.7, 2.6)
  point P34 (191.3186, 1.5409)
  point P39 (176.7, 1.6)
  point P32 (190.3186, 0.5409)
  point P33 (192.3186, 0.5409)
  point P31 (190.3186, 2.5409)
  point P37 (177.7, 0.6)
  point P38 (175.7, 0.6)
  point P36 (177.7, 2.6)
  horizontal L29
  perpendicular L29 L30
  parallel L29 L31
  parallel L30 L32
  coincident L33 P34
  coincident L34 P34
  horizontal L35
  perpendicular L35 L36
  parallel L35 L37
  parallel L36 L38
  coincident L39 P39
  coincident L40 P39
  dimension "d124" distance P32 P33 = 2
  dimension "d125" distance P31 P32 = 2
  dimension "d126" distance P37 P38 = 2
  dimension "d127" distance P36 P37 = 2
sketch "Sketch29" plane through (0, 33, 0) normal (0, -1, 0) x axis (1, 0, 0)
  line L1 (-189.8036, 3) -> (-189.8036, 0)
  line L2 (-192.8089, 3) -> (-189.8036, 3)
  line L3 (-192.8089, 0) -> (-192.8089, 3)
  line L4 (-189.8036, 0) -> (-192.8089, 0)
  circle C1 centre (-191.3186, 1.5409) radius 0.75
  circle C2 centre (-176.7, 1.6) radius 0.75
  point P6 (-191.3186, 1.5409)
  point P8 (-191.3186, 1.5409)
  point P7 (-176.7, 1.6)
  point P9 (-176.7, 1.6)
  coincident P6 P8
  coincident P7 P9
  dimension "d128" diameter C1 = 1.5
  dimension "d129" diameter C2 = 1.5
extrude "Extrude25" cut sketch "Sketch28" profile of L29 L30 L31 L32 L35 L36 L37 L38 against normal blind 2
extrude "Extrude26" add sketch "Sketch29" profile of C1 C2 along normal blind 1.5
split "Split3" bodies "Trestle32FeetTo72FeetSplitTop"
move "Move9"
sketch "Sketch30" plane through (0, 61, 0) normal (0, 1, 0) x axis (-1, 0, 0)
  line L1 (167, 0) -> (168.8333, 0)
  line L2 (167, -2.5) -> (167, 0)
  line L3 (200.4252, -2.5) -> (167, -2.5)
  line L4 (200.4252, 0) -> (200.4252, -2.5)
  line L5 (199.1667, 0) -> (200.4252, 0)
  line L6 (199.1667, 3) -> (199.1667, 0)
  line L7 (200.4252, 3) -> (199.1667, 3)
  line L8 (200.4252, 5.5) -> (200.4252, 3)
  line L9 (167, 5.5) -> (200.4252, 5.5)
  line L10 (167, 3) -> (167, 5.5)
  line L11 (168.8333, 3) -> (167, 3)
  line L12 (168.8333, 0) -> (168.8333, 3)
  line L13 (171.8333, 3) -> (171.8333, 0)
  line L14 (176.8578, 3) -> (171.8333, 3)
  line L15 (176.8578, 0) -> (176.8578, 3)
  line L16 (171.8333, 0) -> (176.8578, 0)
  line L17 (179.8631, 3) -> (179.8631, 0)
  line L18 (182.5, 3) -> (179.8631, 3)
  line L19 (182.5, 0) -> (182.5, 3)
  line L20 (179.8631, 0) -> (182.5, 0)
  line L21 (185.5, 3) -> (185.5, 0)
  line L22 (188.1369, 3) -> (185.5, 3)
  line L23 (188.1369, 0) -> (188.1369, 3)
  line L24 (185.5, 0) -> (188.1369, 0)
  line L25 (191.1422, 3) -> (191.1422, 0)
  line L26 (196.1667, 3) -> (191.1422, 3)
  line L27 (196.1667, 0) -> (196.1667, 3)
  line L28 (191.1422, 0) -> (196.1667, 0)
  line L29 (188.6431, 2.4527) -> (190.6431, 2.4527)
  line L30 (188.6431, 0.4527) -> (188.6431, 2.4527)
  line L31 (190.6431, 0.4527) -> (188.6431, 0.4527)
  line L32 (190.6431, 2.4527) -> (190.6431, 0.4527)
  line L33 (188.6431, 0.4527) -> (190.6431, 2.4527)
  line L34 (190.6431, 0.4527) -> (188.6431, 2.4527)
  line L35 (177.4, 2.5) -> (179.4, 2.5)
  line L36 (177.4, 0.5) -> (177.4, 2.5)
  line L37 (179.4, 0.5) -> (177.4, 0.5)
  line L38 (179.4, 2.5) -> (179.4, 0.5)
  line L39 (177.4, 0.5) -> (179.4, 2.5)
  line L40 (179.4, 0.5) -> (177.4, 2.5)
  point P34 (189.6431, 1.4527)
  point P39 (178.4, 1.5)
  point P32 (188.6431, 0.4527)
  point P33 (190.6431, 0.4527)
  point P31 (188.6431, 2.4527)
  point P37 (177.4, 0.5)
  point P38 (179.4, 0.5)
  point P36 (177.4, 2.5)
  horizontal L29
  perpendicular L29 L30
  parallel L29 L31
  parallel L30 L32
  coincident L33 P34
  coincident L34 P34
  horizontal L35
  perpendicular L35 L36
  parallel L35 L37
  parallel L36 L38
  coincident L39 P39
  coincident L40 P39
  dimension "d134" distance P32 P33 = 2
  dimension "d135" distance P31 P32 = 2
  dimension "d136" distance P37 P38 = 2
  dimension "d137" distance P36 P37 = 2
extrude "Extrude27" cut sketch "Sketch30" profile of L29 L30 L31 L32 L35 L36 L37 L38 against normal blind 2
sketch "Sketch31" plane through (0, 66, 0) normal (0, -1, 0) x axis (1, 0, 0)
  line L1 (-188.1369, 3) -> (-188.1369, 0)
  line L2 (-191.1422, 3) -> (-188.1369, 3)
  line L3 (-191.1422, 0) -> (-191.1422, 3)
  line L4 (-188.1369, 0) -> (-191.1422, 0)
  circle C1 centre (-189.6431, 1.4527) radius 0.75
  circle C2 centre (-178.4, 1.5) radius 0.75
  point P6 (-189.6431, 1.4527)
  point P8 (-189.6431, 1.4527)
  point P7 (-178.4, 1.5)
  point P9 (-178.4, 1.5)
  coincident P6 P8
  coincident P7 P9
  dimension "d140" diameter C1 = 1.5
  dimension "d141" diameter C2 = 1.5
extrude "Extrude28" add sketch "Sketch31" profile of C1 C2 along normal blind 1.5
copy_paste_bodies "CopyPasteBodies7"
move "Move10"
move "Move11"
copy_paste_bodies "CopyPasteBodies8"
copy_paste_bodies "CopyPasteBodies10"
move "Move14"
copy_paste_bodies "CopyPasteBodies11"
move "Move15"
copy_paste_bodies "CopyPasteBodies14"
move "Move20"
copy_paste_bodies "CopyPasteBodies15"
move "Move21"
move "Move22" RotateAngle -180
move "Move23"
copy_paste_bodies "CopyPasteBodies16"
move "Move24"
move "Move25" RotateAngle -180
move "Move26"
move "Move27"
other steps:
base_feature "Base Feature1" bodies "Horz", "CrossPieceHorz41mm"
base_feature "Base Feature2" bodies "TopPiece", "TopPiece (1)"
base_feature "Base Feature3"
base_feature "Base Feature4"
base_feature "Base Feature5" bodies "Testle20To32Feet", "Testle20To32FeetSplitBottom"
base_feature "Base Feature6" bodies "Trestle32FeetTo72Feet", "Trestle32FeetTo72FeetSplitBottom"
base_feature "Base Feature7" bodies "Trestle32FeetTo72Feet (1)", "Trestle32FeetTo72FeetPose1"
base_feature "Base Feature8" bodies "CrossPieceHorz41mm", "CrossPieceHorz41mmPose1"
base_feature "Base Feature10" bodies "CrossPieceHorz31mm", "CrossPieceHorz31mmPose1"
base_feature "Base Feature11" bodies "CrossPieceHorz31mmPose1", "CrossPieceHorz31mmPose2"
base_feature "Base Feature14" bodies "CrossPieceDiagonal", "CrossPieceDiagonalPose1"
base_feature "Base Feature15" bodies "CrossPieceDiagonalPose1", "CrossPieceDiagonalPose2"
base_feature "Base Feature16" bodies "TopPiece (1)", "TopPiece"
named bodies: "CrossPieceHorz31mm", "CrossPieceDiagonal", "Horz", "CrossPieceHorz41mm", "TopPiecePose", "TopPiece", "TopPiece (1)", "TrestleUpTo20Feet", "Trestle32FeetTo72Feet", "Testle20To32Feet", "Testle20To32FeetSplitBottom", "Testle20To32FeetSplitTop", "Trestle32FeetTo72FeetSplitBottom", "Trestle32FeetTo72FeetSplitMiddle", "Trestle32FeetTo72FeetSplitTop", "Trestle32FeetTo72Feet (1)", "Trestle32FeetTo72FeetPose1", "CrossPieceHorz41mmPose1", "CrossPieceHorz31mmPose1", "CrossPieceHorz31mmPose2", "CrossPieceDiagonalPose1", "CrossPieceDiagonalPose2"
